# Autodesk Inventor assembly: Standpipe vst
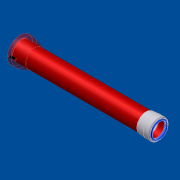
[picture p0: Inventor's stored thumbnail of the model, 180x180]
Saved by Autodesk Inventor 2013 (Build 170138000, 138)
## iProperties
Shininess: 20.0
Length Units: 11269
Angle Units: 11279
Time Units: 11290
Mass Units: 11283
Length Display Precision: 3
Angle Display Precision: 2
Created: 2001-04
Part Number: Standpipe vst
Document SubType Name: Baugruppe
Designer: dl
Density: 0.0
Volumn: 0.0
Area: 0.0
PropertySet Name: Model Information
Control State: 0
Master: False
Checked Out: False
Author: dl
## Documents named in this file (9)
- C:\Webworld\Webworld2014\ATC2013\Assemblies\ATC-Baby Carriage\DAMPER\Standpipe vst.iam
- C:\Webworld\Webworld2014\ATC2013\Assemblies\ATC-Baby Carriage\DAMPER\Suspension_clamp.ipt
- C:\Webworld\Webworld2014\ATC2013\Assemblies\ATC-Baby Carriage\DAMPER\End_cap_bottom.ipt
- C:\Webworld\Webworld2014\ATC2013\Assemblies\ATC-Baby Carriage\DAMPER\Wiper_bush.ipt
- C:\Webworld\Webworld2014\ATC2013\Assemblies\ATC-Baby Carriage\DAMPER\Standpipe.ipt
- C:\Webworld\Webworld2014\ATC2013\Assemblies\ATC-Baby Carriage\DAMPER\Sliding_bush2.ipt
- C:\Webworld\Webworld2014\ATC2013\Assemblies\ATC-Baby Carriage\DAMPER\Support_ring.ipt
- C:\Webworld\Webworld2014\ATC2013\Assemblies\ATC-Baby Carriage\DAMPER\Sliding_bush2_short.ipt
- C:\Webworld\Webworld2014\ATC2013\Assemblies\ATC-Baby Carriage\DAMPER\Wiper.ipt
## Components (13 placed, 8 different names)
1. Suspension_clamp:1 — Insert:1, Insert:2
2. End_cap_bottom:1 — Insert:1, Insert:3, Insert:4
3. Wiper_bush:1 — Insert:2, Insert:12
4. Standpipe:1 — Insert:3
5. Sliding_bush2:1 — Insert:4, Insert:5
6. Sliding_bush2:2 — Insert:5, Insert:8
7. Support_ring:1 — Insert:8, Insert:9
8. Sliding_bush2:3 — Insert:6, Insert:9
9. Sliding_bush2:4 — Insert:6, Insert:7
10. Sliding_bush2:5 — Insert:7, Insert:10
11. Sliding_bush2_short:1 — Insert:10, Insert:11
12. Support_ring:2 — Insert:11
13. Wiper:1 — Insert:12
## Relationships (12: Insert 12)
- Insert:1: Suspension_clamp:1 ↔ End_cap_bottom:1
- Insert:2: Suspension_clamp:1 ↔ Wiper_bush:1
- Insert:3: End_cap_bottom:1 ↔ Standpipe:1
- Insert:4: End_cap_bottom:1 ↔ Sliding_bush2:1
- Insert:5: Sliding_bush2:1 ↔ Sliding_bush2:2
- Insert:6: Sliding_bush2:3 ↔ Sliding_bush2:4
- Insert:7: Sliding_bush2:4 ↔ Sliding_bush2:5
- Insert:8: Sliding_bush2:2 ↔ Support_ring:1
- Insert:9: Support_ring:1 ↔ Sliding_bush2:3
- Insert:10: Sliding_bush2:5 ↔ Sliding_bush2_short:1
- Insert:11: Sliding_bush2_short:1 ↔ Support_ring:2
- Insert:12: Wiper_bush:1 ↔ Wiper:1
